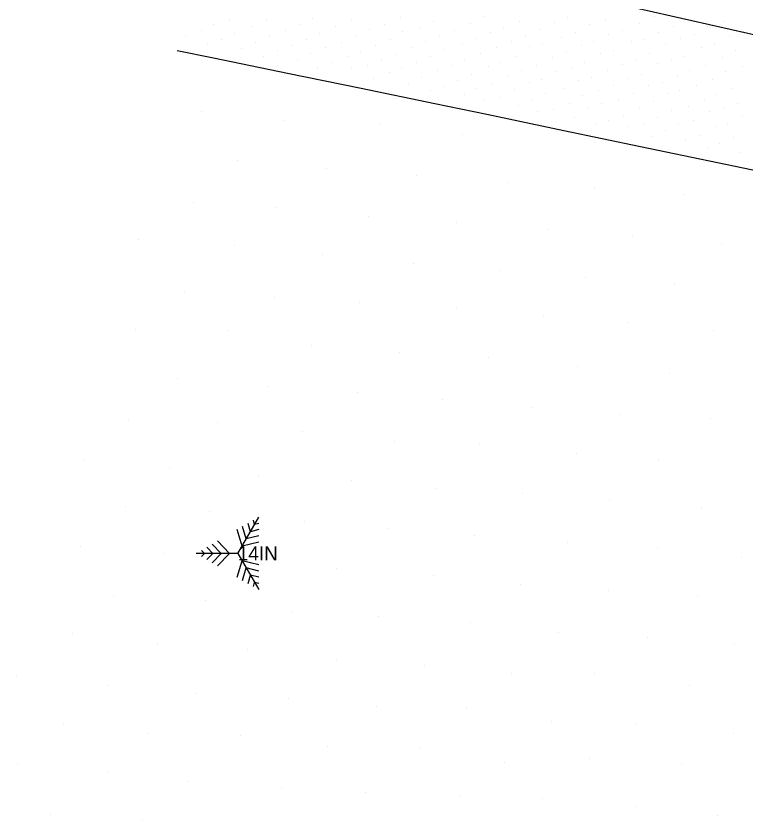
# Model space of a CAD drawing. Extents: x 1732346 to 1733076, y 467730 to 468633.
# Drawn here: x 1732415.8 to 1732508.6, y 467968.3 to 468070.7 of the extents above; entities that cross this region are included whole.
import ezdxf

# ---------------------------------------------------------------- set-up
doc = ezdxf.new("R2010")
doc.units = 0
for name, color, linetype in [('Default', 7, 'Continuous'), ('S_Ground_SpotElevation', 7, 'Continuous'), ('S_Roadway_Edge_Pavement', 7, 'Continuous'), ('S_Roadway_Painted_Lines', 7, 'Continuous'), ('S_Text', 7, 'Continuous'), ('S_Trees_Conifer_Pay', 7, 'Continuous')]:
    doc.layers.add(name, color=color, linetype=linetype)

# ---------------------------------------------------------------- blocks, each defined once
blk = doc.blocks.new('POINT_DISPLAY')
at = {"layer": 'Default'}
blk.add_line((0, 0), (0, 0), dxfattribs=at)

msp = doc.modelspace()

# ---------------------------------------------------------------- linework, layer by layer
at = {"layer": 'S_Roadway_Edge_Pavement'}
msp.add_lwpolyline([(1732605.39, 468031.13), (1732595.61, 468033.2), (1732591.46, 468034.07), (1732581.67, 468036.11), (1732571.88, 468038.14), (1732562.09, 468040.17), (1732552.29, 468042.2), (1732542.5, 468044.23), (1732532.71, 468046.27), (1732524.6, 468047.95), (1732514.81, 468049.99), (1732505.02, 468052.03), (1732495.23, 468054.06), (1732485.44, 468056.1), (1732475.65, 468058.14), (1732469.06, 468059.51), (1732459.68, 468061.45), (1732450.29, 468063.38), (1732440.9, 468065.32), (1732436.26, 468066.28)], dxfattribs=at)
at = {"layer": 'S_Roadway_Painted_Lines'}
msp.add_lwpolyline([(1732441.28, 468083.32), (1732451.05, 468081.2), (1732460.82, 468079.08), (1732466.41, 468077.86), (1732476.18, 468075.74), (1732485.95, 468073.62), (1732490.66, 468072.6), (1732500.41, 468070.42), (1732510.17, 468068.23), (1732515.11, 468067.13), (1732524.87, 468064.97), (1732534.63, 468062.81), (1732539.58, 468061.72), (1732549.34, 468059.57), (1732559.11, 468057.41), (1732563.94, 468056.35), (1732573.7, 468054.18), (1732583.46, 468052.01), (1732588.4, 468050.91), (1732598.15, 468048.69), (1732607.9, 468046.47)], dxfattribs=at)
at = {"layer": 'S_Trees_Conifer_Pay'}
for p, q in [((1732443.99, 468002.32), (1732446.66, 468006.93)), ((1732446.12, 468006.01), (1732445.97, 468006.53)), ((1732444.53, 468003.24), (1732443.92, 468005.35)), ((1732445.06, 468004.16), (1732444.6, 468005.74)), ((1732445.59, 468005.08), (1732445.29, 468006.14)), ((1732446.66, 468005.35), (1732445.59, 468005.08)), ((1732446.66, 468006.14), (1732446.12, 468006.01)), ((1732446.66, 468004.56), (1732445.06, 468004.16)), ((1732441.86, 468002.32), (1732440.72, 468003.5)), ((1732442.93, 468002.32), (1732441.41, 468003.9)), ((1732446.66, 468003.77), (1732444.53, 468003.24)), ((1732443.99, 468002.32), (1732438.67, 468002.32)), ((1732439.73, 468002.32), (1732439.35, 468002.71)), ((1732439.35, 468001.92), (1732439.73, 468002.32)), ((1732440.8, 468002.32), (1732440.04, 468003.11)), ((1732440.04, 468001.53), (1732440.8, 468002.32)), ((1732440.72, 468001.13), (1732441.86, 468002.32)), ((1732441.41, 468000.74), (1732442.93, 468002.32)), ((1732443.99, 468002.32), (1732446.66, 467997.71)), ((1732443.92, 467999.29), (1732444.53, 468001.39)), ((1732446.66, 468000.87), (1732444.53, 468001.39)), ((1732444.6, 467998.89), (1732445.06, 468000.47)), ((1732446.66, 468000.08), (1732445.06, 468000.47)), ((1732445.29, 467998.5), (1732445.59, 467999.55)), ((1732446.66, 467999.29), (1732445.59, 467999.55)), ((1732445.97, 467998.1), (1732446.12, 467998.63)), ((1732446.66, 467998.5), (1732446.12, 467998.63))]:
    msp.add_line(p, q, dxfattribs=at)

# ---------------------------------------------------------------- block references
at = {"layer": 'S_Ground_SpotElevation'}
for p in [(1732442.92, 468070.3), (1732447.64, 468070.17), (1732453.49, 468070.43), (1732458.42, 468070.2), (1732464.74, 468070.51), (1732468.88, 468069.98), (1732475.35, 468070.67), (1732479.79, 468069.97), (1732484.27, 468069.9), (1732485.96, 468070.55), (1732490.71, 468070.12), (1732496.99, 468070.65), (1732500.98, 468070.48), (1732505.86, 468070.01), (1732439.36, 468068.83), (1732440.95, 468069.59), (1732445.79, 468069.4), (1732450.06, 468068.81), (1732451.95, 468069.63), (1732456.46, 468069.3), (1732460.71, 468068.99), (1732462.69, 468069.65), (1732467.09, 468069.21), (1732471.58, 468068.87), (1732473.58, 468069.71), (1732477.73, 468069.26), (1732482.35, 468069.03), (1732488.7, 468069.6), (1732492.94, 468068.89), (1732495.06, 468069.69), (1732499.46, 468069.38), (1732503.79, 468069.37), (1732437.36, 468068.04), (1732443.6, 468068.46), (1732448.03, 468068.2), (1732454.38, 468068.45), (1732459.05, 468068.11), (1732464.88, 468068.66), (1732469.67, 468068.06), (1732474.36, 468067.81), (1732476.18, 468068.53), (1732480.56, 468068.26), (1732485.15, 468067.96), (1732486.95, 468068.59), (1732491.12, 468068.31), (1732497.55, 468068.57), (1732500.24, 468067.81), (1732502.09, 468068.3), (1732506.59, 468068.17), (1732508.35, 468068.71), (1732440.16, 468067.02), (1732441.89, 468067.71), (1732446.3, 468067.29), (1732450.76, 468066.97), (1732452.69, 468067.69), (1732457.22, 468067.37), (1732461.52, 468066.97), (1732463.47, 468067.71), (1732467.85, 468067.48), (1732472.53, 468067.17), (1732478.77, 468067.47), (1732481.13, 468066.82), (1732482.79, 468067.05), (1732487.71, 468066.89), (1732489.22, 468067.47), (1732494.02, 468067.45), (1732495.56, 468067.75), (1732498.33, 468067.06), (1732504.67, 468067.03), (1732444.45, 468066.57), (1732449, 468066.26), (1732453.25, 468065.92), (1732455.16, 468066.64), (1732459.58, 468066.2), (1732464.06, 468065.83), (1732466.14, 468066.7), (1732470.15, 468066.37), (1732474.91, 468065.92), (1732476.89, 468066.72), (1732485.75, 468066.18), (1732490.15, 468065.97), (1732491.76, 468066.3), (1732496.37, 468065.96), (1732502.97, 468066.69), (1732507.34, 468066.32), (1732447.24, 468065.57), (1732451.56, 468065.19), (1732455.91, 468064.75), (1732457.88, 468065.56), (1732462.3, 468065.11), (1732466.68, 468064.72), (1732468.56, 468065.58), (1732472.84, 468065.17), (1732477.42, 468064.76), (1732479.45, 468065.56), (1732484.07, 468065.35), (1732488.09, 468064.78), (1732494.65, 468065.17), (1732499.14, 468065.09), (1732500.86, 468065.52), (1732505.62, 468065.43), (1732454.09, 468064.14), (1732458.41, 468063.97), (1732460.49, 468064.39), (1732464.77, 468064.08), (1732469.36, 468063.72), (1732471.28, 468064.41), (1732475.88, 468064.31), (1732480.02, 468063.71), (1732481.97, 468064.44), (1732486.53, 468064.13), (1732491.02, 468063.72), (1732492.88, 468064.48), (1732497.36, 468064.59), (1732501.45, 468063.7), (1732503.49, 468064.44), (1732508.2, 468064.3), (1732461.28, 468062.72), (1732463.27, 468063.48), (1732467.32, 468062.9), (1732473.76, 468063.24), (1732478.42, 468063.07), (1732484.39, 468063.63), (1732488.94, 468062.93), (1732493.64, 468062.72), (1732495.29, 468063.28), (1732499.93, 468063.1), (1732505.98, 468063.57), (1732465.65, 468062.15), (1732470.15, 468061.78), (1732471.91, 468062.54), (1732476.37, 468062.15), (1732481.06, 468062.2), (1732482.65, 468062.62), (1732487.3, 468062.47), (1732491.73, 468061.89), (1732496.18, 468061.81), (1732498.06, 468062.24), (1732502.32, 468061.8), (1732504.38, 468062.64), (1732468.49, 468061.25), (1732472.76, 468060.74), (1732474.37, 468061.41), (1732479.23, 468061.31), (1732483.1, 468060.86), (1732485.37, 468061.45), (1732489.83, 468061.2), (1732494.37, 468060.83), (1732498.74, 468060.82), (1732500.21, 468061.21), (1732504.89, 468060.7), (1732506.88, 468061.51), (1732475.4, 468059.96), (1732477.23, 468060.33), (1732481.47, 468059.96), (1732486.13, 468059.59), (1732487.84, 468060.56), (1732490.2, 468059.62), (1732492.41, 468060.08), (1732496.9, 468059.75), (1732503.3, 468060.01), (1732439.42, 468058.57), (1732479.69, 468059.29), (1732482.08, 468058.58), (1732484.12, 468058.8), (1732488.46, 468058.92), (1732495.12, 468058.93), (1732499.13, 468058.63), (1732501.29, 468059.21), (1732503.93, 468058.57), (1732505.89, 468059.09), (1732507.53, 468059.57), (1732486.87, 468057.72), (1732493.1, 468058.08), (1732497.43, 468057.74), (1732508.18, 468057.97), (1732449.84, 468057.44), (1732462.02, 468056.99), (1732489.45, 468056.86), (1732491.1, 468057.34), (1732493.54, 468056.63), (1732495.67, 468057.02), (1732500.02, 468056.99), (1732501.89, 468057.43), (1732504.87, 468056.58), (1732506.34, 468057.06), (1732472.63, 468055.58), (1732498.43, 468056.09), (1732502.66, 468055.54), (1732496.72, 468055.34), (1732500.99, 468054.8), (1732507.05, 468055.19), (1732503.77, 468053.94), (1732505.23, 468054.45), (1732507.9, 468053.36), (1732443.96, 468052.26), (1732455.22, 468051.33), (1732466.78, 468050.4), (1732478.24, 468049.53), (1732489.33, 468048.7), (1732500.65, 468047.95), (1732438.39, 468046.99), (1732448.95, 468046.31), (1732460.56, 468045.23), (1732471.85, 468044.44), (1732483.55, 468043.5), (1732431.31, 468042.29), (1732494.23, 468042.59), (1732443.62, 468041.5), (1732505.57, 468041.77), (1732454.8, 468040.29), (1732466.32, 468039.24), (1732477.35, 468038.35), (1732488.19, 468037.37), (1732499.49, 468036.7), (1732437.2, 468035.67), (1732448.68, 468034.89), (1732459.49, 468034.2), (1732471.79, 468033.49), (1732482.81, 468032.53), (1732493.69, 468031.75), (1732430.94, 468030.77), (1732442.73, 468030.65), (1732504.44, 468030.71), (1732453.36, 468028.83), (1732464.55, 468027.93), (1732475.91, 468027.26), (1732487.25, 468026.1), (1732498.96, 468025.21), (1732436.36, 468024.62), (1732447.8, 468023.59), (1732459.27, 468022.77), (1732470.04, 468021.91), (1732481.37, 468020.89), (1732492.73, 468020.04), (1732430.06, 468019.29), (1732441.35, 468018.97), (1732504.14, 468019.43), (1732452.21, 468017.78), (1732463.93, 468016.62), (1732474.67, 468016.22), (1732487.05, 468015), (1732424.45, 468014.27), (1732497.46, 468014.28), (1732435.36, 468013.27), (1732446.6, 468012.27), (1732458.49, 468011.54), (1732469.22, 468010.55), (1732480.15, 468009.89), (1732491.28, 468009.06), (1732429.71, 468008.25), (1732440.39, 468007.64), (1732503, 468008.2), (1732452.41, 468006.44), (1732463.13, 468005.54), (1732474.08, 468004.55), (1732485.98, 468003.75), (1732424.04, 468003.25), (1732434.66, 468002.3), (1732497.43, 468002.92), (1732508.07, 468001.84), (1732445.64, 468001.01), (1732456.48, 468000.39), (1732468.88, 467999.52), (1732479.99, 467998.34), (1732491.1, 467997.65), (1732428.13, 467996.97), (1732439.91, 467996.39), (1732502.41, 467996.96), (1732450.82, 467994.88), (1732461.91, 467994.24), (1732473.62, 467993.5), (1732422.98, 467992.09), (1732484.74, 467992.24), (1732496.07, 467991.63), (1732433.81, 467990.87), (1732445.2, 467990.14), (1732507.19, 467990.81), (1732456.48, 467988.83), (1732467.76, 467988.09), (1732478.74, 467987.07), (1732489.33, 467987.04), (1732415.79, 467986.73), (1732427.49, 467985.46), (1732501.41, 467985.55), (1732438.63, 467984.49), (1732450.39, 467983.87), (1732461.57, 467982.79), (1732473.09, 467982.66), (1732483.93, 467980.95), (1732421.86, 467980.63), (1732494.68, 467980.6), (1732432.67, 467979.37), (1732444.34, 467979.11), (1732506.98, 467979.37), (1732455.35, 467977.71), (1732467.22, 467977.59), (1732477.93, 467975.74), (1732488.71, 467976.2), (1732415.94, 467975.57), (1732500.44, 467975.48), (1732427.44, 467974.54), (1732437.65, 467973.34), (1732449.55, 467972.53), (1732460.25, 467971.86), (1732472.32, 467971.53), (1732482.7, 467971.12), (1732494.55, 467970.06), (1732420.1, 467969.11), (1732505.01, 467968.98), (1732431.89, 467968.29)]:
    msp.add_blockref('POINT_DISPLAY', p, dxfattribs=at)

# ---------------------------------------------------------------- texts
at = {"layer": 'S_Text'}
msp.add_text('14IN', height=1.8, dxfattribs=at).set_placement((1732443.99, 468001.42))

doc.saveas('drawing.dxf')
